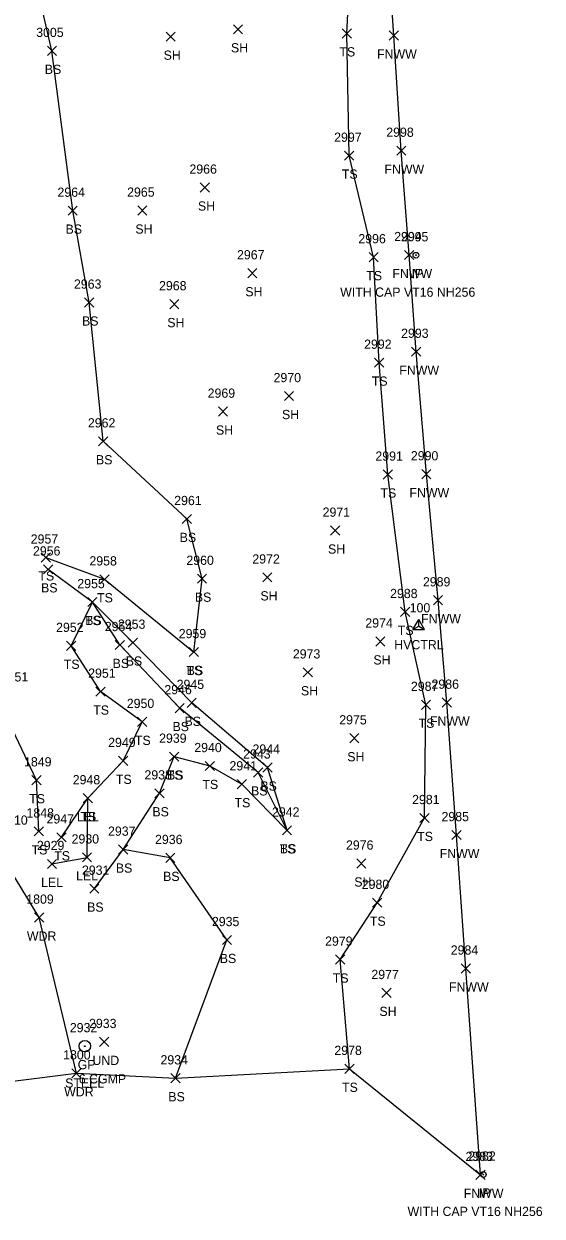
# Model space of a CAD drawing. Extents: x 1650221 to 1650634, y 244606 to 249996.
# Drawn here: x 1650521.6 to 1650633.9, y 244608.7 to 244867.1 of the extents above; entities that cross this region are included whole.
import ezdxf

# ---------------------------------------------------------------- set-up
doc = ezdxf.new("R2010")
doc.units = 0
for name, color, linetype in [('C_A', 7, 'Continuous'), ('C_I', 7, 'Continuous'), ('CPSM', 7, 'Continuous'), ('D_A', 7, 'Continuous'), ('D_C', 7, 'Continuous'), ('D_I', 7, 'Continuous'), ('D_TIC', 7, 'Continuous'), ('L_A', 7, 'Continuous'), ('L_I', 7, 'Continuous'), ('L_TIC', 7, 'Continuous'), ('LARO', 7, 'Continuous'), ('LAWA', 7, 'Continuous'), ('LELB', 7, 'Continuous'), ('LFNC', 7, 'Continuous'), ('LSOGP', 7, 'Continuous'), ('M_A', 7, 'Continuous'), ('M_C', 7, 'Continuous'), ('M_I', 7, 'Continuous'), ('MPIR', 7, 'Continuous'), ('R_A', 7, 'Continuous'), ('R_C', 7, 'Continuous'), ('R_I', 7, 'Continuous'), ('RGP', 7, 'Continuous')]:
    doc.layers.add(name, color=color, linetype=linetype)

msp = doc.modelspace()

# ---------------------------------------------------------------- linework, layer by layer
at = {"layer": 'CPSM'}
for p, q in [((1650605.86, 244735.87), (1650607.11, 244738.03)), ((1650608.36, 244735.87), (1650607.11, 244738.03)), ((1650607.11, 244736.59), (1650607.11, 244738.03)), ((1650605.86, 244735.87), (1650607.11, 244736.59)), ((1650605.86, 244735.87), (1650608.36, 244735.87)), ((1650607.11, 244736.59), (1650607.11, 244736.59)), ((1650607.11, 244736.59), (1650608.36, 244735.87))]:
    msp.add_line(p, q, dxfattribs=at)
at = {"layer": 'D_TIC'}
for points in [[(1650537.94, 244645.5), (1650539.94, 244647.5)], [(1650539.94, 244645.5), (1650537.94, 244647.5)]]:
    msp.add_lwpolyline(points, dxfattribs=at)
at = {"layer": 'L_TIC'}
for points in [[(1650566.95, 244864.96), (1650568.95, 244866.96)], [(1650568.95, 244864.96), (1650566.95, 244866.96)], [(1650552.36, 244863.36), (1650554.36, 244865.36)], [(1650554.36, 244863.36), (1650552.36, 244865.36)], [(1650590.52, 244864.08), (1650592.52, 244866.08)], [(1650592.52, 244864.08), (1650590.52, 244866.08)], [(1650600.74, 244863.61), (1650602.74, 244865.61)], [(1650602.74, 244863.61), (1650600.74, 244865.61)], [(1650526.65, 244860.29), (1650528.65, 244862.29)], [(1650528.65, 244860.29), (1650526.65, 244862.29)], [(1650591.05, 244837.58), (1650593.05, 244839.58)], [(1650593.05, 244837.58), (1650591.05, 244839.58)], [(1650602.34, 244838.66), (1650604.34, 244840.66)], [(1650604.34, 244838.66), (1650602.34, 244840.66)], [(1650559.79, 244830.67), (1650561.79, 244832.67)], [(1650561.79, 244830.67), (1650559.79, 244832.67)], [(1650531.14, 244825.66), (1650533.14, 244827.66)], [(1650533.14, 244825.66), (1650531.14, 244827.66)], [(1650546.23, 244825.68), (1650548.23, 244827.68)], [(1650548.23, 244825.68), (1650546.23, 244827.68)], [(1650604.06, 244816.05), (1650606.06, 244818.05)], [(1650606.06, 244816.05), (1650604.06, 244818.05)], [(1650596.34, 244815.58), (1650598.34, 244817.58)], [(1650598.34, 244815.58), (1650596.34, 244817.58)], [(1650570.05, 244812.1), (1650572.05, 244814.1)], [(1650572.05, 244812.1), (1650570.05, 244814.1)], [(1650534.72, 244805.75), (1650536.72, 244807.75)], [(1650536.72, 244805.75), (1650534.72, 244807.75)], [(1650553.16, 244805.4), (1650555.16, 244807.4)], [(1650555.16, 244805.4), (1650553.16, 244807.4)], [(1650605.56, 244795.09), (1650607.56, 244797.09)], [(1650607.56, 244795.09), (1650605.56, 244797.09)], [(1650597.54, 244792.72), (1650599.54, 244794.72)], [(1650599.54, 244792.72), (1650597.54, 244794.72)], [(1650578, 244785.48), (1650580, 244787.48)], [(1650580, 244785.48), (1650578, 244787.48)], [(1650563.7, 244782.11), (1650565.7, 244784.11)], [(1650565.7, 244782.11), (1650563.7, 244784.11)], [(1650537.74, 244775.67), (1650539.74, 244777.67)], [(1650539.74, 244775.67), (1650537.74, 244777.67)], [(1650599.42, 244768.47), (1650601.42, 244770.47)], [(1650601.42, 244768.47), (1650599.42, 244770.47)], [(1650607.76, 244768.54), (1650609.76, 244770.54)], [(1650609.76, 244768.54), (1650607.76, 244770.54)], [(1650555.87, 244758.84), (1650557.87, 244760.84)], [(1650557.87, 244758.84), (1650555.87, 244760.84)], [(1650587.99, 244756.32), (1650589.99, 244758.32)], [(1650589.99, 244756.32), (1650587.99, 244758.32)], [(1650525.3, 244750.5), (1650527.3, 244752.5)], [(1650527.3, 244750.5), (1650525.3, 244752.5)], [(1650525.84, 244747.92), (1650527.84, 244749.92)], [(1650527.84, 244747.92), (1650525.84, 244749.92)], [(1650573.32, 244746.18), (1650575.32, 244748.18)], [(1650575.32, 244746.18), (1650573.32, 244748.18)], [(1650538.02, 244745.76), (1650540.02, 244747.76)], [(1650540.02, 244745.76), (1650538.02, 244747.76)], [(1650559.16, 244745.89), (1650561.16, 244747.89)], [(1650561.16, 244745.89), (1650559.16, 244747.89)], [(1650535.4, 244740.84), (1650537.4, 244742.84)], [(1650537.4, 244740.84), (1650535.4, 244742.84)], [(1650535.4, 244740.84), (1650537.4, 244742.84)], [(1650537.4, 244740.84), (1650535.4, 244742.84)], [(1650535.4, 244740.84), (1650537.4, 244742.84)], [(1650537.4, 244740.84), (1650535.4, 244742.84)], [(1650610.29, 244741.22), (1650612.29, 244743.22)], [(1650612.29, 244741.22), (1650610.29, 244743.22)], [(1650603.17, 244738.69), (1650605.17, 244740.69)], [(1650605.17, 244738.69), (1650603.17, 244740.69)], [(1650530.8, 244731.35), (1650532.8, 244733.35)], [(1650532.8, 244731.35), (1650530.8, 244733.35)], [(1650541.35, 244731.53), (1650543.35, 244733.53)], [(1650543.35, 244731.53), (1650541.35, 244733.53)], [(1650544.19, 244732.04), (1650546.19, 244734.04)], [(1650546.19, 244732.04), (1650544.19, 244734.04)], [(1650597.8, 244732.3), (1650599.8, 244734.3)], [(1650599.8, 244732.3), (1650597.8, 244734.3)], [(1650557.39, 244730), (1650559.39, 244732)], [(1650559.39, 244730), (1650557.39, 244732)], [(1650557.39, 244730), (1650559.39, 244732)], [(1650559.39, 244730), (1650557.39, 244732)], [(1650582.1, 244725.6), (1650584.1, 244727.6)], [(1650584.1, 244725.6), (1650582.1, 244727.6)], [(1650537.18, 244721.42), (1650539.18, 244723.42)], [(1650539.18, 244721.42), (1650537.18, 244723.42)], [(1650554.32, 244717.85), (1650556.32, 244719.85)], [(1650556.32, 244717.85), (1650554.32, 244719.85)], [(1650556.92, 244718.99), (1650558.92, 244720.99)], [(1650558.92, 244718.99), (1650556.92, 244720.99)], [(1650607.68, 244718.58), (1650609.68, 244720.58)], [(1650609.68, 244718.58), (1650607.68, 244720.58)], [(1650612.19, 244719.04), (1650614.19, 244721.04)], [(1650614.19, 244719.04), (1650612.19, 244721.04)], [(1650546.21, 244714.86), (1650548.21, 244716.86)], [(1650548.21, 244714.86), (1650546.21, 244716.86)], [(1650592.15, 244711.31), (1650594.15, 244713.31)], [(1650594.15, 244711.31), (1650592.15, 244713.31)], [(1650553.13, 244707.33), (1650555.13, 244709.33)], [(1650555.13, 244707.33), (1650553.13, 244709.33)], [(1650553.13, 244707.33), (1650555.13, 244709.33)], [(1650555.13, 244707.33), (1650553.13, 244709.33)], [(1650542.09, 244706.41), (1650544.09, 244708.41)], [(1650544.09, 244706.41), (1650542.09, 244708.41)], [(1650560.83, 244705.3), (1650562.83, 244707.3)], [(1650562.83, 244705.3), (1650560.83, 244707.3)], [(1650573.36, 244704.97), (1650575.36, 244706.97)], [(1650575.36, 244704.97), (1650573.36, 244706.97)], [(1650523.3, 244702.21), (1650525.3, 244704.21)], [(1650525.3, 244702.21), (1650523.3, 244704.21)], [(1650571.34, 244703.91), (1650573.34, 244705.91)], [(1650573.34, 244703.91), (1650571.34, 244705.91)], [(1650567.8, 244701.34), (1650569.8, 244703.34)], [(1650569.8, 244701.34), (1650567.8, 244703.34)], [(1650534.41, 244698.33), (1650536.41, 244700.33)], [(1650536.41, 244698.33), (1650534.41, 244700.33)], [(1650534.41, 244698.33), (1650536.41, 244700.33)], [(1650536.41, 244698.33), (1650534.41, 244700.33)], [(1650549.95, 244699.38), (1650551.95, 244701.38)], [(1650551.95, 244699.38), (1650549.95, 244701.38)], [(1650607.37, 244694.03), (1650609.37, 244696.03)], [(1650609.37, 244694.03), (1650607.37, 244696.03)], [(1650523.82, 244691.13), (1650525.82, 244693.13)], [(1650525.82, 244691.13), (1650523.82, 244693.13)], [(1650528.73, 244689.84), (1650530.73, 244691.84)], [(1650530.73, 244689.84), (1650528.73, 244691.84)], [(1650577.58, 244691.35), (1650579.58, 244693.35)], [(1650579.58, 244691.35), (1650577.58, 244693.35)], [(1650577.58, 244691.35), (1650579.58, 244693.35)], [(1650579.58, 244691.35), (1650577.58, 244693.35)], [(1650577.58, 244691.35), (1650579.58, 244693.35)], [(1650579.58, 244691.35), (1650577.58, 244693.35)], [(1650614.31, 244690.34), (1650616.31, 244692.34)], [(1650616.31, 244690.34), (1650614.31, 244692.34)], [(1650542.05, 244687.18), (1650544.05, 244689.18)], [(1650544.05, 244687.18), (1650542.05, 244689.18)], [(1650542.05, 244687.18), (1650544.05, 244689.18)], [(1650544.05, 244687.18), (1650542.05, 244689.18)], [(1650526.65, 244684.07), (1650528.65, 244686.07)], [(1650528.65, 244684.07), (1650526.65, 244686.07)], [(1650534.24, 244685.5), (1650536.24, 244687.5)], [(1650536.24, 244685.5), (1650534.24, 244687.5)], [(1650552.29, 244685.38), (1650554.29, 244687.38)], [(1650554.29, 244685.38), (1650552.29, 244687.38)], [(1650593.67, 244684.17), (1650595.67, 244686.17)], [(1650595.67, 244684.17), (1650593.67, 244686.17)], [(1650535.83, 244678.72), (1650537.83, 244680.72)], [(1650537.83, 244678.72), (1650535.83, 244680.72)], [(1650597.12, 244675.67), (1650599.12, 244677.67)], [(1650599.12, 244675.67), (1650597.12, 244677.67)], [(1650523.86, 244672.45), (1650525.86, 244674.45)], [(1650525.86, 244672.45), (1650523.86, 244674.45)], [(1650564.56, 244667.59), (1650566.56, 244669.59)], [(1650566.56, 244667.59), (1650564.56, 244669.59)], [(1650589.08, 244663.34), (1650591.08, 244665.34)], [(1650591.08, 244663.34), (1650589.08, 244665.34)], [(1650616.31, 244661.42), (1650618.31, 244663.42)], [(1650618.31, 244661.42), (1650616.31, 244663.42)], [(1650599.11, 244656.12), (1650601.11, 244658.12)], [(1650601.11, 244656.12), (1650599.11, 244658.12)], [(1650531.93, 244638.7), (1650533.93, 244640.7)], [(1650533.93, 244638.7), (1650531.93, 244640.7)], [(1650553.42, 244637.62), (1650555.42, 244639.62)], [(1650555.42, 244637.62), (1650553.42, 244639.62)], [(1650591.09, 244639.67), (1650593.09, 244641.67)], [(1650593.09, 244639.67), (1650591.09, 244641.67)], [(1650619.51, 244616.69), (1650621.51, 244618.69)], [(1650621.51, 244616.69), (1650619.51, 244618.69)]]:
    msp.add_lwpolyline(points, dxfattribs=at)
at = {"layer": 'LARO'}
msp.add_lwpolyline([(1650527.65, 244685.07), (1650535.24, 244686.5), (1650535.41, 244699.33)], dxfattribs=at)
at = {"layer": 'LAWA'}
msp.add_lwpolyline([(1650532.93, 244639.7), (1650524.86, 244673.45), (1650514.54, 244690.35), (1650510.25, 244717.67), (1650508.53, 244755.66), (1650503.06, 244803.5), (1650499.99, 244846.46), (1650496.47, 244893.78), (1650492.54, 244932.91), (1650488.72, 244979.52), (1650493.15, 245007.74), (1650492.82, 245049.31), (1650491.93, 245077.75), (1650491, 245121.86)], dxfattribs=at)
at = {"layer": 'LELB'}
for points in [[(1650558.39, 244731), (1650560.16, 244746.89), (1650556.87, 244759.84), (1650538.74, 244776.67), (1650535.72, 244806.75), (1650532.14, 244826.66), (1650527.65, 244861.29), (1650520.49, 244892.39), (1650525.9, 244912.47), (1650527.83, 244939.42), (1650532.34, 244967.74), (1650532.66, 244978.77), (1650542.3, 245005.6), (1650546.24, 245022.45), (1650561.01, 245015.02), (1650576.46, 245035.33), (1650588.27, 245060.15)], [(1650592.09, 244640.67), (1650590.08, 244664.34), (1650598.12, 244676.67), (1650608.37, 244695.03), (1650608.68, 244719.58), (1650604.17, 244739.69), (1650600.42, 244769.47), (1650598.54, 244793.72), (1650597.34, 244816.58), (1650592.05, 244838.58), (1650591.52, 244865.08), (1650592.78, 244889.24), (1650585.69, 244902.84), (1650587.86, 244916.21), (1650591, 244938.27), (1650587.21, 244953.52), (1650589.28, 244980.46), (1650592.83, 244995.87)], [(1650524.82, 244692.13), (1650524.3, 244703.21), (1650517.93, 244716.68), (1650518.69, 244721.62), (1650516.17, 244742.48), (1650517.26, 244759.56), (1650514.71, 244782.3), (1650511.3, 244790.99), (1650516.72, 244804.93), (1650514.52, 244824.56), (1650515.45, 244838.01), (1650511.05, 244844.32), (1650513.46, 244857.93), (1650507.41, 244878.18)], [(1650526.3, 244751.5), (1650539.02, 244746.76), (1650558.39, 244731)], [(1650578.58, 244692.35), (1650572.34, 244704.91), (1650555.32, 244718.85), (1650542.35, 244732.53), (1650536.4, 244741.84), (1650526.84, 244748.92)], [(1650529.73, 244690.84), (1650535.41, 244699.33), (1650543.09, 244707.41), (1650547.21, 244715.86), (1650538.18, 244722.42), (1650531.8, 244732.35), (1650536.4, 244741.84)], [(1650578.58, 244692.35), (1650574.36, 244705.97), (1650557.92, 244719.99), (1650545.19, 244733.04), (1650536.4, 244741.84)], [(1650536.83, 244679.72), (1650543.05, 244688.18), (1650550.95, 244700.38), (1650554.13, 244708.33)], [(1650554.13, 244708.33), (1650561.83, 244706.3), (1650568.8, 244702.34), (1650578.58, 244692.35)], [(1650554.42, 244638.62), (1650565.56, 244668.59), (1650553.29, 244686.38), (1650543.05, 244688.18)]]:
    msp.add_lwpolyline(points, dxfattribs=at)
at = {"layer": 'LFNC'}
msp.add_lwpolyline([(1650620.51, 244617.69), (1650617.31, 244662.42), (1650615.31, 244691.34), (1650613.19, 244720.04), (1650611.29, 244742.22), (1650608.76, 244769.54), (1650606.56, 244796.09), (1650605.06, 244817.05), (1650603.34, 244839.66), (1650601.74, 244864.61), (1650599.88, 244891.09), (1650599, 244907.23), (1650598.09, 244925.6), (1650595.48, 244961.16), (1650593.81, 244982.84), (1650592.83, 244995.87), (1650591.08, 245019.11), (1650589.36, 245042.09), (1650588.27, 245060.15), (1650586.18, 245090.82), (1650584.33, 245116.87), (1650580.12, 245176.92)], dxfattribs=at)
at = {"layer": 'LSOGP'}
msp.add_lwpolyline([(1650507.02, 244636.48), (1650532.93, 244639.7), (1650554.42, 244638.62), (1650592.09, 244640.67), (1650620.51, 244617.69), (1650617.31, 244662.42), (1650615.31, 244691.34), (1650613.19, 244720.04), (1650611.29, 244742.22), (1650608.76, 244769.54), (1650606.56, 244796.09), (1650605.06, 244817.05), (1650603.34, 244839.66), (1650601.74, 244864.61), (1650599.88, 244891.09)], dxfattribs=at)
at = {"layer": 'MPIR'}
for centre, radius in [((1650606.51, 244817), 0.625), ((1650606.51, 244817), 0.0833), ((1650621.11, 244617.77), 0.625), ((1650621.11, 244617.77), 0.0833)]:
    msp.add_circle(centre, radius, dxfattribs=at)
at = {"layer": 'RGP'}
msp.add_line((1650534.78, 244645.59), (1650534.78, 244645.59), dxfattribs=at)
for radius in [1.25, 0.0833]:
    msp.add_circle((1650534.78, 244645.59), radius, dxfattribs=at)

# ---------------------------------------------------------------- texts
at = {"layer": 'C_A'}
msp.add_text('HVCTRL', height=2, dxfattribs=at).set_placement((1650601.81, 244731.59))
at = {"layer": 'C_I'}
msp.add_text('100', height=2, dxfattribs=at).set_placement((1650605.15, 244739.59))
at = {"layer": 'D_A'}
msp.add_text('UND', height=2, dxfattribs=at).set_placement((1650536.42, 244641.5))
at = {"layer": 'D_C'}
msp.add_text('6 CGMP', height=2, dxfattribs=at).set_placement((1650533.47, 244637.5))
at = {"layer": 'D_I'}
msp.add_text('2933', height=2, dxfattribs=at).set_placement((1650535.68, 244649.5))
at = {"layer": 'L_A'}
for s, p in [('SH', (1650566.43, 244860.96)), ('TS', (1650589.93, 244860.08)), ('SH', (1650551.84, 244859.36)), ('FNWW', (1650598.08, 244859.61)), ('BS', (1650526.09, 244856.29)), ('FNWW', (1650599.68, 244834.66)), ('TS', (1650590.46, 244833.58)), ('SH', (1650559.28, 244826.67)), ('BS', (1650530.59, 244821.66)), ('SH', (1650545.72, 244821.68)), ('TS', (1650595.75, 244811.58)), ('FNWW', (1650601.41, 244812.05)), ('SH', (1650569.54, 244808.1)), ('BS', (1650534.16, 244801.75)), ('SH', (1650552.64, 244801.4)), ('FNWW', (1650602.91, 244791.09)), ('TS', (1650596.95, 244788.72)), ('SH', (1650577.49, 244781.48)), ('SH', (1650563.19, 244778.11)), ('BS', (1650537.18, 244771.67)), ('TS', (1650598.83, 244764.47)), ('FNWW', (1650605.1, 244764.54)), ('BS', (1650555.31, 244754.84)), ('SH', (1650587.47, 244752.32)), ('TS', (1650524.71, 244746.5)), ('BS', (1650525.28, 244743.92)), ('TS', (1650537.43, 244741.76)), ('BS', (1650558.6, 244741.89)), ('SH', (1650572.81, 244742.18)), ('TS', (1650534.81, 244736.84)), ('BS', (1650534.84, 244736.84)), ('BS', (1650534.84, 244736.84)), ('FNWW', (1650607.63, 244737.22)), ('TS', (1650602.58, 244734.69)), ('BS', (1650543.63, 244728.04)), ('SH', (1650597.29, 244728.3)), ('TS', (1650530.21, 244727.35)), ('BS', (1650540.79, 244727.53)), ('TS', (1650556.8, 244726)), ('BS', (1650556.83, 244726)), ('SH', (1650581.59, 244721.6)), ('TS', (1650536.59, 244717.42)), ('BS', (1650556.36, 244714.99)), ('FNWW', (1650609.54, 244715.04)), ('BS', (1650553.76, 244713.85)), ('TS', (1650607.09, 244714.58)), ('TS', (1650545.62, 244710.86)), ('SH', (1650591.63, 244707.31)), ('TS', (1650541.5, 244702.41)), ('TS', (1650552.54, 244703.33)), ('BS', (1650552.57, 244703.33)), ('TS', (1650560.24, 244701.3)), ('BS', (1650570.78, 244699.91)), ('BS', (1650572.8, 244700.97)), ('TS', (1650522.71, 244698.21)), ('TS', (1650567.21, 244697.34)), ('LEL', (1650533.05, 244694.33)), ('TS', (1650533.82, 244694.33)), ('BS', (1650549.4, 244695.38)), ('TS', (1650606.78, 244690.03)), ('TS', (1650523.23, 244687.13)), ('TS', (1650576.99, 244687.35)), ('BS', (1650577.02, 244687.35)), ('BS', (1650577.02, 244687.35)), ('TS', (1650528.14, 244685.84)), ('FNWW', (1650611.65, 244686.34)), ('LEL', (1650532.88, 244681.5)), ('BS', (1650541.49, 244683.18)), ('BS', (1650541.49, 244683.18)), ('BS', (1650551.73, 244681.38)), ('LEL', (1650525.29, 244680.07)), ('SH', (1650593.15, 244680.17)), ('BS', (1650535.27, 244674.72)), ('TS', (1650596.53, 244671.67)), ('WDR', (1650522.22, 244668.45)), ('BS', (1650564, 244663.59)), ('TS', (1650588.49, 244659.34)), ('FNWW', (1650613.66, 244657.42)), ('SH', (1650598.6, 244652.12)), ('TS', (1650590.5, 244635.67)), ('WDR', (1650530.29, 244634.7)), ('BS', (1650552.86, 244633.62)), ('FNWW', (1650616.86, 244612.69))]:
    msp.add_text(s, height=2, dxfattribs=at).set_placement(p)
at = {"layer": 'L_I'}
for s, p in [('3005', (1650524.23, 244864.29)), ('2997', (1650588.79, 244841.58)), ('2998', (1650600.08, 244842.66)), ('2966', (1650557.43, 244834.67)), ('2964', (1650528.84, 244829.66)), ('2965', (1650543.93, 244829.68)), ('2996', (1650594.03, 244819.58)), ('2994', (1650601.8, 244820.05)), ('2967', (1650567.74, 244816.1)), ('2963', (1650532.41, 244809.75)), ('2968', (1650550.85, 244809.4)), ('2993', (1650603.3, 244799.09)), ('2992', (1650595.28, 244796.72)), ('2970', (1650575.66, 244789.48)), ('2969', (1650561.38, 244786.11)), ('2962', (1650535.43, 244779.67)), ('2991', (1650597.72, 244772.47)), ('2990', (1650605.41, 244772.54)), ('2961', (1650554.13, 244762.84)), ('2971', (1650586.29, 244760.32)), ('2957', (1650523.04, 244754.5)), ('2956', (1650523.53, 244751.92)), ('2958', (1650535.76, 244749.76)), ('2960', (1650556.77, 244749.89)), ('2972', (1650571.06, 244750.18)), ('2955', (1650533.14, 244744.84)), ('2955', (1650533.14, 244744.84)), ('2955', (1650533.14, 244744.84)), ('2989', (1650608.02, 244745.22)), ('2988', (1650600.91, 244742.69)), ('2953', (1650541.93, 244736.04)), ('2974', (1650595.54, 244736.3)), ('2952', (1650528.54, 244735.35)), ('2954', (1650539.09, 244735.53)), ('2959', (1650555.12, 244734)), ('2959', (1650555.12, 244734)), ('2973', (1650579.84, 244729.6)), ('2951', (1650535.49, 244725.42)), ('1851', (1650516.56, 244724.62)), ('2945', (1650554.66, 244722.99)), ('2986', (1650609.88, 244723.04)), ('2946', (1650552, 244721.85)), ('2987', (1650605.42, 244722.58)), ('2950', (1650543.86, 244718.86)), ('2975', (1650589.89, 244715.31)), ('2949', (1650539.82, 244710.41)), ('2939', (1650550.86, 244711.33)), ('2939', (1650550.86, 244711.33)), ('2940', (1650558.48, 244709.3)), ('2943', (1650569.08, 244707.91)), ('2944', (1650571.1, 244708.97)), ('1849', (1650521.6, 244706.21)), ('2941', (1650566.11, 244705.34)), ('2948', (1650532.15, 244702.33)), ('2948', (1650532.15, 244702.33)), ('2938', (1650547.69, 244703.38)), ('2981', (1650605.68, 244698.03)), ('1848', (1650522.13, 244695.13)), ('2942', (1650575.32, 244695.35)), ('2942', (1650575.32, 244695.35)), ('2942', (1650575.32, 244695.35)), ('2985', (1650612.05, 244694.34)), ('1810', (1650516.44, 244693.58)), ('2947', (1650526.47, 244693.84)), ('2930', (1650531.9, 244689.5)), ('2937', (1650539.79, 244691.18)), ('2937', (1650539.79, 244691.18)), ('2936', (1650549.98, 244689.38)), ('2929', (1650524.38, 244688.07)), ('2976', (1650591.35, 244688.17)), ('2931', (1650534.14, 244682.72)), ('2980', (1650594.77, 244679.67)), ('1809', (1650522.08, 244676.45)), ('2935', (1650562.3, 244671.59)), ('2979', (1650586.82, 244667.34)), ('2984', (1650614.05, 244665.42)), ('2977', (1650596.85, 244660.12)), ('1800', (1650530.07, 244642.7)), ('2978', (1650588.83, 244643.67)), ('2934', (1650551.16, 244641.62)), ('2983', (1650617.25, 244620.69))]:
    msp.add_text(s, height=2, dxfattribs=at).set_placement(p)
at = {"layer": 'M_A'}
for p in [(1650605.56, 244812), (1650620.16, 244612.77)]:
    msp.add_text('IP', height=2, dxfattribs=at).set_placement(p)
at = {"layer": 'M_C'}
for p in [(1650590.09, 244808), (1650604.69, 244608.77)]:
    msp.add_text('WITH CAP VT16 NH256', height=2, dxfattribs=at).set_placement(p)
at = {"layer": 'M_I'}
for s, p in [('2995', (1650603.25, 244820)), ('2982', (1650617.85, 244620.77))]:
    msp.add_text(s, height=2, dxfattribs=at).set_placement(p)
at = {"layer": 'R_A'}
msp.add_text('GP', height=2, dxfattribs=at).set_placement((1650533.22, 244640.59))
at = {"layer": 'R_C'}
msp.add_text('STEEL', height=2, dxfattribs=at).set_placement((1650530.5, 244636.59))
at = {"layer": 'R_I'}
msp.add_text('2932', height=2, dxfattribs=at).set_placement((1650531.52, 244648.59))

doc.saveas('drawing.dxf')
